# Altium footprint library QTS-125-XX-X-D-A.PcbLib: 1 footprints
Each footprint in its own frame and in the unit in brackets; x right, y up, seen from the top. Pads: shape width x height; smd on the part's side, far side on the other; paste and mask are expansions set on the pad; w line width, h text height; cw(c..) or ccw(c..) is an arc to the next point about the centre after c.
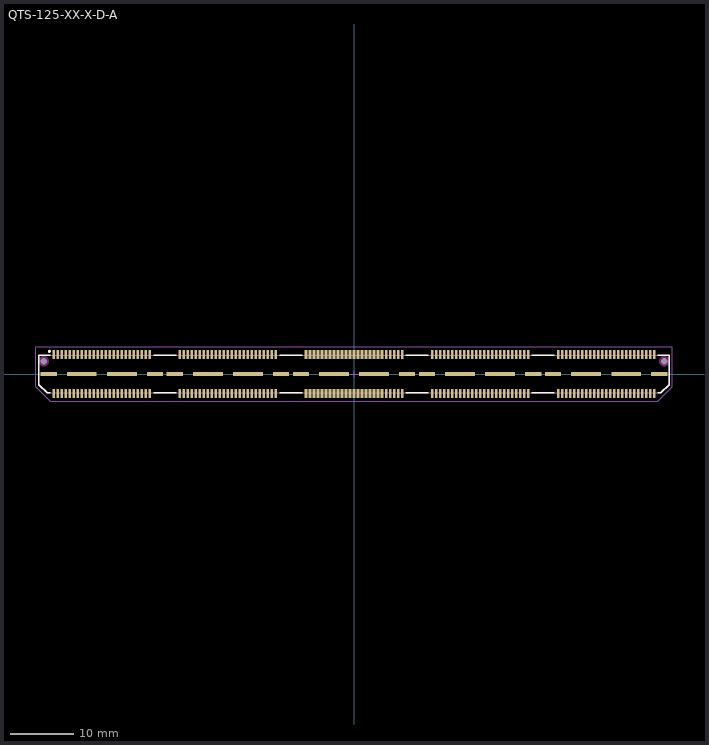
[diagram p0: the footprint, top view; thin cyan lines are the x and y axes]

## QTS-125-XX-X-D-A [mm] "0.635mm pitch, 250 pin, high speed terminal strip; 5 banks"
height 4.27
pads (272):
  rect 0.4x1.45 smd mask+0: 1(-47.624,3.086) 2(-47.624,-3.086) 3(-46.989,3.086) 4(-46.989,-3.086) 5(-46.354,3.086) 6(-46.354,-3.086) 7(-45.719,3.086) 8(-45.719,-3.086) 9(-45.084,3.086) 10(-45.084,-3.086) 11(-44.449,3.086) 12(-44.449,-3.086) 13(-43.814,3.086) 14(-43.814,-3.086) 15(-43.179,3.086) 16(-43.179,-3.086) 17(-42.544,3.086) 18(-42.544,-3.086) 19(-41.909,3.086) 20(-41.909,-3.086) 21(-41.274,3.086) 22(-41.274,-3.086) 23(-40.639,3.086) 24(-40.639,-3.086) 25(-40.004,3.086) 26(-40.004,-3.086) 27(-39.369,3.086) 28(-39.369,-3.086) 29(-38.734,3.086) 30(-38.734,-3.086) 31(-38.099,3.086) 32(-38.099,-3.086) 33(-37.464,3.086) 34(-37.464,-3.086) 35(-36.829,3.086) 36(-36.829,-3.086) 37(-36.194,3.086) 38(-36.194,-3.086) 39(-35.559,3.086) 40(-35.559,-3.086) 41(-34.924,3.086) 42(-34.924,-3.086) 43(-34.289,3.086) 44(-34.289,-3.086) 45(-33.654,3.086) 46(-33.654,-3.086) 47(-33.019,3.086) 48(-33.019,-3.086) 49(-32.384,3.086) 50(-32.384,-3.086) 51(-27.622,3.086) 52(-27.622,-3.086) 53(-26.987,3.086) 54(-26.987,-3.086) 55(-26.352,3.086) 56(-26.352,-3.086) 57(-25.717,3.086) 58(-25.717,-3.086) 59(-25.082,3.086) 60(-25.082,-3.086) 61(-24.447,3.086) 62(-24.447,-3.086) 63(-23.812,3.086) 64(-23.812,-3.086) 65(-23.177,3.086) 66(-23.177,-3.086) 67(-22.542,3.086) 68(-22.542,-3.086) 69(-21.907,3.086) 70(-21.907,-3.086) 71(-21.272,3.086) 72(-21.272,-3.086) 73(-20.637,3.086) 74(-20.637,-3.086) 75(-20.002,3.086) 76(-20.002,-3.086) 77(-19.367,3.086) 78(-19.367,-3.086) 79(-18.732,3.086) 80(-18.732,-3.086) 81(-18.097,3.086) 82(-18.097,-3.086) 83(-17.462,3.086) 84(-17.462,-3.086) 85(-16.827,3.086) 86(-16.827,-3.086) 87(-16.192,3.086) 88(-16.192,-3.086) 89(-15.557,3.086) 90(-15.557,-3.086) 91(-14.922,3.086) 92(-14.922,-3.086) 93(-14.287,3.086) 94(-14.287,-3.086) 95(-13.652,3.086) 96(-13.652,-3.086) 97(-13.017,3.086) 98(-13.017,-3.086) 99(-12.382,3.086) 100(-12.382,-3.086) 101(-7.619,3.086) 102(-7.619,-3.086) 103(-6.984,3.086) 104(-6.984,-3.086) 105(-6.349,3.086) 106(-6.349,-3.086) 107(-5.714,3.086) 108(-5.714,-3.086) 109(-5.079,3.086) 110(-5.079,-3.086) 111(-4.444,3.086) 112(-4.444,-3.086) 113(-3.809,3.086) 114(-3.809,-3.086) 115(-3.174,3.086) 116(-3.174,-3.086) 117(-2.539,3.086) 118(-2.539,-3.086) 119(-1.904,3.086) 120(-1.904,-3.086) 121(-1.269,3.086) 122(-1.269,-3.086) 123(-0.634,3.086) 124(-0.634,-3.086) 125(0.001,3.086) 126(0.001,-3.086) 127(0.636,3.086) 128(0.636,-3.086) 129(1.271,3.086) 130(1.271,-3.086) 131(1.906,3.086) 132(1.906,-3.086) 133(2.541,3.086) 134(2.541,-3.086) 135(3.176,3.086) 136(3.176,-3.086) 137(3.811,3.086) 138(3.811,-3.086) 139(4.446,3.086) 140(4.446,-3.086) 141(5.081,3.086) 142(5.081,-3.086) 143(5.716,3.086) 144(5.716,-3.086) 145(6.351,3.086) 146(6.351,-3.086) 147(6.986,3.086) 148(6.986,-3.086) 149(7.621,3.086) 150(7.621,-3.086) 151(12.383,3.086) 152(12.383,-3.086) 153(13.018,3.086) 154(13.018,-3.086) 155(13.653,3.086) 156(13.653,-3.086) 157(14.288,3.086) 158(14.288,-3.086) 159(14.923,3.086) 160(14.923,-3.086) 161(15.558,3.086) 162(15.558,-3.086) 163(16.193,3.086) 164(16.193,-3.086) 165(16.828,3.086) 166(16.828,-3.086) 167(17.463,3.086) 168(17.463,-3.086) 169(18.098,3.086) 170(18.098,-3.086) 171(18.733,3.086) 172(18.733,-3.086) 173(19.368,3.086) 174(19.368,-3.086) 175(20.003,3.086) 176(20.003,-3.086) 177(20.638,3.086) 178(20.638,-3.086) 179(21.273,3.086) 180(21.273,-3.086) 181(21.908,3.086) 182(21.908,-3.086) 183(22.543,3.086) 184(22.543,-3.086) 185(23.178,3.086) 186(23.178,-3.086) 187(23.813,3.086) 188(23.813,-3.086) 189(24.448,3.086) 190(24.448,-3.086) 191(25.083,3.086) 192(25.083,-3.086) 193(25.718,3.086) 194(25.718,-3.086) 195(26.353,3.086) 196(26.353,-3.086) 197(26.988,3.086) 198(26.988,-3.086) 199(27.623,3.086) 200(27.623,-3.086) 201(32.386,3.086) 202(32.386,-3.086) 203(33.021,3.086) 204(33.021,-3.086) 205(33.656,3.086) 206(33.656,-3.086) 207(34.291,3.086) 208(34.291,-3.086) 209(34.926,3.086) 210(34.926,-3.086) 211(35.561,3.086) 212(35.561,-3.086) 213(36.196,3.086) 214(36.196,-3.086) 215(36.831,3.086) 216(36.831,-3.086) 217(37.466,3.086) 218(37.466,-3.086) 219(38.101,3.086) 220(38.101,-3.086) 221(38.736,3.086) 222(38.736,-3.086) 223(39.371,3.086) 224(39.371,-3.086) 225(40.006,3.086) 226(40.006,-3.086) 227(40.641,3.086) 228(40.641,-3.086) 229(41.276,3.086) 230(41.276,-3.086) 231(41.911,3.086) 232(41.911,-3.086) 233(42.546,3.086) 234(42.546,-3.086) 235(43.181,3.086) 236(43.181,-3.086) 237(43.816,3.086) 238(43.816,-3.086) 239(44.451,3.086) 240(44.451,-3.086) 241(45.086,3.086) 242(45.086,-3.086) 243(45.721,3.086) 244(45.721,-3.086) 245(46.356,3.086) 246(46.356,-3.086) 247(46.991,3.086) 248(46.991,-3.086) 249(47.626,3.086) 250(47.626,-3.086)
  rect 2.55x0.65 smd mask+0: 251(-48.45,0) 254(-31.559,0) 255(-28.447,0) 258(-11.556,0) 259(-8.445,0) 262(8.446,0) 263(11.558,0) 266(28.449,0) 267(31.56,0) 270(48.451,0)
  rect 4.7x0.65 smd mask+0: 252(-43.179,0) 253(-36.829,0) 256(-23.177,0) 257(-16.827,0) 260(-3.174,0) 261(3.176,0) 264(16.828,0) 265(23.178,0) 268(36.831,0) 269(43.181,0)
  round 0.5 hole 1 unplated mask+0: 271(-49.245,2.032) 272(49.246,2.032)
Top Overlay:
  circle w0.25: c-48.35,3.6 r0.125
  lines w0.2: -48.2,-3 -48.7,-3 -50,-1.7 -50,3 -48.2,3 ; -31.8,-3 -28.2,-3 ; -31.8,3 -28.2,3 ; -11.8,-3 -8.2,-3 ; -11.8,3 -8.2,3 ; 8.2,-3 11.8,-3 ; 8.2,3 11.8,3 ; 28.2,-3 31.8,-3 ; 28.2,3 31.8,3 ; 48.2,-3 48.7,-3 50,-1.7 50,3 48.2,3
Keep-Out Layer:
  pour cut-out: -48.438,2.032 -48.466,2.241 -48.546,2.435 -48.674,2.603 -48.842,2.731 -49.036,2.811 -49.245,2.839 -49.454,2.811 -49.648,2.731 -49.816,2.603 -49.944,2.435 -50.024,2.241 -50.052,2.032 -50.024,1.823 -49.944,1.629 -49.816,1.461 -49.648,1.333 -49.454,1.253 -49.245,1.225 -49.036,1.253 -48.842,1.333 -48.674,1.461 -48.546,1.629 -48.466,1.823
  pour cut-out: 50.053,2.032 50.025,2.241 49.945,2.435 49.817,2.603 49.649,2.731 49.455,2.811 49.246,2.839 49.037,2.811 48.843,2.731 48.675,2.603 48.547,2.435 48.467,2.241 48.439,2.032 48.467,1.823 48.547,1.629 48.675,1.461 48.843,1.333 49.037,1.253 49.246,1.225 49.455,1.253 49.649,1.333 49.817,1.461 49.945,1.629 50.025,1.823
Mechanical 12:
  lines w0.001: -50,-1.7 -50,3 50,3 50,-1.7 48.7,-3 -48.7,-3 -50,-1.7
Mechanical 13:
  lines w0.1: -50,-1.7 -50,3 50,3 50,-1.7 48.7,-3 -48.7,-3 -50,-1.7
  text ".Designator" at 0.254,-0.254 h1.52
Mechanical 15:
  lines w0.05: -0.5,0 0.5,0 ; 0,-0.5 0,0.5 ; -50.5,-2 -48.195,-4.3 48.2,-4.3 50.5,-2 50.5,4.3 -50.5,4.3 -50.5,-2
